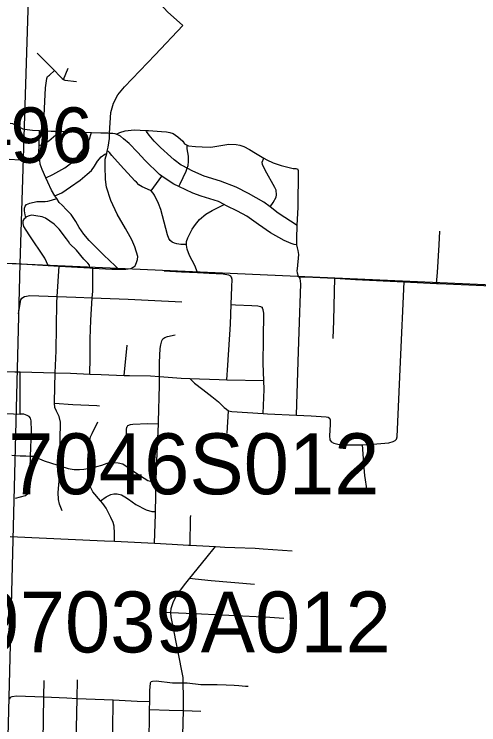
# Model space of a CAD drawing. Extents: x -157.2 to -99.3, y 12.2 to 46.2.
# Drawn here: x -146.586 to -145.747, y 36.444 to 37.727 of the extents above; entities that cross this region are included whole.
import ezdxf

# ---------------------------------------------------------------- set-up
doc = ezdxf.new("R2010")
doc.units = 0
for name, color, linetype in [('tdCoCityStreetMinor', 7, 'Continuous'), ('tdCoSectLine', 7, 'Continuous'), ('tdCoStrucPriMaintName', 7, 'Continuous'), ('tdStHwyPriRefPost1', 7, 'Continuous')]:
    doc.layers.add(name, color=color, linetype=linetype)

msp = doc.modelspace()

# ---------------------------------------------------------------- linework, layer by layer
at = {"layer": 'tdCoCityStreetMinor'}
for p, q in [((-146.4969, 37.6097), (-146.4885, 37.6301)), ((-146.3388, 37.4084), (-146.3197, 37.4352)), ((-146.3154, 37.2639), (-146.2841, 37.2624)), ((-146.0081, 37.201), (-146.0068, 37.2504)), ((-146.3875, 37.0746), (-146.3823, 37.1294)), ((-146.4497, 37.0773), (-146.4493, 37.1066)), ((-146.5753, 37.0051), (-146.5755, 37.0817)), ((-146.2017, 36.9707), (-146.199, 37.0111)), ((-146.3309, 36.829), (-146.3297, 36.8827)), ((-146.5328, 36.4942), (-146.5322, 36.5242)), ((-146.4727, 36.4916), (-146.472, 36.5254)), ((-146.3401, 36.5192), (-146.3398, 36.5199)), ((-146.2806, 36.4698), (-146.2491, 36.4687))]:
    msp.add_line(p, q, dxfattribs=at)
for points in [[(-146.4138, 37.5128), (-146.4115, 37.5497), (-146.4071, 37.5667), (-146.3988, 37.5821), (-146.3871, 37.5961), (-146.3318, 37.6543), (-146.2815, 37.7071), (-146.3093, 37.7315), (-146.3222, 37.7453), (-146.3782, 37.804), (-146.4238, 37.8455), (-146.4289, 37.7966), (-146.4298, 37.7769), (-146.4289, 37.7658), (-146.4277, 37.7623), (-146.4156, 37.7495)], [(-146.5448, 37.6572), (-146.5134, 37.6259), (-146.5132, 37.6256), (-146.5043, 37.6163), (-146.4996, 37.6114), (-146.4969, 37.6097), (-146.4945, 37.6082), (-146.4737, 37.6057)], [(-146.5329, 37.517), (-146.5327, 37.5325), (-146.5297, 37.5946), (-146.5273, 37.6116), (-146.526, 37.6148), (-146.5226, 37.6175), (-146.5132, 37.6256)], [(-146.5935, 37.5304), (-146.5896, 37.5298), (-146.5815, 37.5256), (-146.5707, 37.5206), (-146.563, 37.5191), (-146.5532, 37.5179), (-146.5405, 37.5174), (-146.5329, 37.517), (-146.5196, 37.5164), (-146.5074, 37.516), (-146.4466, 37.5136), (-146.4298, 37.513), (-146.4168, 37.513), (-146.4138, 37.5128), (-146.4081, 37.5125), (-146.4042, 37.5117), (-146.4014, 37.5105)], [(-146.398, 37.2669), (-146.4037, 37.273), (-146.4244, 37.2925), (-146.4506, 37.3187), (-146.4604, 37.3302), (-146.4688, 37.3421), (-146.4752, 37.3532), (-146.4836, 37.3658), (-146.4915, 37.3739), (-146.4996, 37.3823), (-146.5051, 37.3872), (-146.5094, 37.3944), (-146.5126, 37.3997), (-146.5186, 37.4097), (-146.5255, 37.424), (-146.529, 37.4319), (-146.5356, 37.4471), (-146.5391, 37.4565), (-146.5399, 37.4637), (-146.5416, 37.4775), (-146.5412, 37.4906), (-146.5411, 37.4965), (-146.5405, 37.5174)], [(-146.5412, 37.4906), (-146.5337, 37.493), (-146.5238, 37.4987), (-146.5154, 37.5058), (-146.511, 37.5098), (-146.5074, 37.516)], [(-146.4014, 37.5105), (-146.3953, 37.514), (-146.386, 37.5169), (-146.3692, 37.5187), (-146.3477, 37.5174), (-146.3435, 37.5172), (-146.3199, 37.5159), (-146.3112, 37.5152), (-146.3048, 37.5137), (-146.2989, 37.5117), (-146.2908, 37.5058), (-146.2814, 37.4984), (-146.2784, 37.4933), (-146.2736, 37.4911), (-146.2713, 37.49), (-146.2589, 37.4886), (-146.2466, 37.4878), (-146.2308, 37.4876), (-146.22, 37.4891), (-146.1985, 37.4928), (-146.185, 37.492), (-146.1788, 37.4908), (-146.1712, 37.4883), (-146.1608, 37.4831), (-146.1504, 37.4765), (-146.1352, 37.4675), (-146.1295, 37.4642), (-146.1184, 37.459), (-146.1036, 37.4543), (-146.0824, 37.4486), (-146.0772, 37.4486), (-146.074, 37.4476)], [(-146.0747, 37.3461), (-146.1093, 37.3682), (-146.1237, 37.3794), (-146.1352, 37.3882), (-146.1628, 37.4037), (-146.1852, 37.4153), (-146.2133, 37.4259), (-146.2427, 37.4348), (-146.2634, 37.4437), (-146.2737, 37.4491), (-146.2816, 37.4533), (-146.2843, 37.455), (-146.2974, 37.4646), (-146.3033, 37.4696), (-146.3218, 37.4866), (-146.3334, 37.4984), (-146.3423, 37.5088), (-146.347, 37.5159), (-146.3477, 37.5174)], [(-146.529, 37.4319), (-146.5164, 37.4378), (-146.4947, 37.4501), (-146.4802, 37.4607), (-146.4732, 37.4683), (-146.47, 37.473), (-146.4636, 37.4807), (-146.4592, 37.4873), (-146.452, 37.4983), (-146.4497, 37.5032), (-146.4482, 37.5084), (-146.4466, 37.5136)], [(-146.3768, 37.3253), (-146.3852, 37.3401), (-146.4, 37.3665), (-146.4116, 37.3907), (-146.4195, 37.4151), (-146.4215, 37.4289), (-146.422, 37.4531), (-146.4217, 37.4659), (-146.4191, 37.4761), (-146.418, 37.4803), (-146.4163, 37.4871), (-146.4138, 37.5029), (-146.4138, 37.5128)], [(-146.3637, 37.4781), (-146.3788, 37.4937), (-146.3889, 37.5026), (-146.3943, 37.5071), (-146.4014, 37.5105)], [(-146.2889, 37.4163), (-146.2866, 37.4212), (-146.2755, 37.4439), (-146.2737, 37.4491), (-146.272, 37.4543), (-146.2713, 37.4614), (-146.2713, 37.4711), (-146.2735, 37.4841), (-146.2736, 37.4911)], [(-146.3655, 37.4239), (-146.3684, 37.4267), (-146.3943, 37.455), (-146.4096, 37.4725), (-146.4138, 37.4775), (-146.416, 37.4792), (-146.418, 37.4803)], [(-146.0753, 37.3107), (-146.0802, 37.3113), (-146.0858, 37.3132), (-146.0982, 37.3187), (-146.1231, 37.3327), (-146.1448, 37.3478), (-146.1657, 37.3626), (-146.1825, 37.3719), (-146.2027, 37.3815), (-146.2067, 37.3837), (-146.2173, 37.3892), (-146.2483, 37.3986), (-146.2634, 37.404), (-146.2889, 37.4163), (-146.2977, 37.4205), (-146.3134, 37.4306), (-146.3197, 37.4352), (-146.3236, 37.438), (-146.3495, 37.4634), (-146.3637, 37.4781)], [(-146.5956, 37.4655), (-146.5554, 37.4632), (-146.5399, 37.4637)], [(-146.5126, 37.3997), (-146.5004, 37.405), (-146.4846, 37.4156), (-146.4668, 37.4277), (-146.4545, 37.4383), (-146.4466, 37.4454), (-146.4412, 37.4528), (-146.436, 37.4619), (-146.4291, 37.4698), (-146.4227, 37.4745), (-146.4191, 37.4761)], [(-146.1237, 37.3794), (-146.1185, 37.3875), (-146.1131, 37.3968), (-146.1124, 37.401), (-146.1129, 37.4094), (-146.1153, 37.4143), (-146.1328, 37.4459), (-146.1375, 37.4558), (-146.138, 37.4605), (-146.1352, 37.4675)], [(-146.0747, 37.3461), (-146.0733, 37.3791), (-146.0728, 37.4444), (-146.074, 37.4476)], [(-146.3388, 37.4084), (-146.3453, 37.4116), (-146.3549, 37.4158), (-146.361, 37.4195), (-146.3655, 37.4239)], [(-146.2752, 37.3112), (-146.2851, 37.3115), (-146.2925, 37.3125), (-146.2964, 37.3137), (-146.3009, 37.3159), (-146.3046, 37.3187), (-146.3068, 37.3224), (-146.3095, 37.329), (-146.3213, 37.3746), (-146.3253, 37.3855), (-146.3327, 37.4008), (-146.3354, 37.404), (-146.3388, 37.4084)], [(-146.5651, 37.3605), (-146.5662, 37.3653), (-146.5675, 37.3722), (-146.5679, 37.3769), (-146.5662, 37.3808), (-146.5638, 37.3835), (-146.5578, 37.386), (-146.5453, 37.3889), (-146.5305, 37.3894), (-146.5255, 37.3899), (-146.5189, 37.3914), (-146.5094, 37.3944)], [(-146.2752, 37.3112), (-146.2752, 37.3167), (-146.2723, 37.3238), (-146.2644, 37.3394), (-146.2587, 37.3475), (-146.2513, 37.3569), (-146.2402, 37.366), (-146.2284, 37.3732), (-146.2153, 37.3796), (-146.2067, 37.3837)], [(-146.4884, 37.3168), (-146.492, 37.3216), (-146.5048, 37.3391), (-146.5142, 37.3485), (-146.5295, 37.3591), (-146.5359, 37.3613), (-146.5472, 37.3633), (-146.5544, 37.3643), (-146.5593, 37.3635), (-146.5638, 37.3616), (-146.5651, 37.3605)], [(-146.525, 37.2737), (-146.5312, 37.2871), (-146.5593, 37.329), (-146.5689, 37.3438), (-146.5702, 37.3497), (-146.5699, 37.3542), (-146.567, 37.3591), (-146.5651, 37.3605)], [(-146.0753, 37.3107), (-146.0755, 37.3115), (-146.0757, 37.3226), (-146.0747, 37.3461)], [(-145.8233, 37.2411), (-145.8213, 37.2607), (-145.8185, 37.3106), (-145.8169, 37.3358)], [(-146.3664, 37.2758), (-146.365, 37.2787), (-146.3633, 37.2846), (-146.363, 37.2901), (-146.3682, 37.3071), (-146.3739, 37.3201), (-146.3768, 37.3253)], [(-146.4495, 37.2693), (-146.4501, 37.274), (-146.4535, 37.2777), (-146.4607, 37.2849), (-146.474, 37.3011), (-146.4856, 37.313), (-146.4884, 37.3168)], [(-146.2548, 37.261), (-146.2599, 37.2738), (-146.2696, 37.2918), (-146.2737, 37.3029), (-146.2752, 37.3103), (-146.2752, 37.3112)], [(-146.0698, 37.2501), (-146.0698, 37.2501), (-146.0712, 37.2523), (-146.0723, 37.2538), (-146.0745, 37.26), (-146.0747, 37.2646), (-146.0745, 37.2676), (-146.072, 37.2933), (-146.073, 37.3009), (-146.0745, 37.3056), (-146.0753, 37.3107)], [(-146.602, 37.278), (-146.5827, 37.277), (-146.525, 37.2737), (-146.5053, 37.2726), (-146.4826, 37.2713), (-146.4495, 37.2693), (-146.4444, 37.269), (-146.4096, 37.2669), (-146.398, 37.2669), (-146.3845, 37.2669), (-146.3753, 37.2683), (-146.3714, 37.2703), (-146.3677, 37.273), (-146.3664, 37.2758)], [(-146.5136, 37.0272), (-146.512, 37.08), (-146.5107, 37.1196), (-146.509, 37.206), (-146.5084, 37.2174), (-146.5053, 37.2726)], [(-146.4493, 37.1066), (-146.4488, 37.1411), (-146.4478, 37.1751), (-146.4452, 37.2151), (-146.4444, 37.2264), (-146.4444, 37.269)], [(-146.2841, 37.2624), (-146.2548, 37.261), (-146.2337, 37.2599)], [(-146.2337, 37.2599), (-146.2086, 37.2587), (-146.1988, 37.257), (-146.1953, 37.255), (-146.1952, 37.2548)], [(-146.2023, 37.0673), (-146.2003, 37.0938), (-146.1956, 37.1677), (-146.1942, 37.203), (-146.1929, 37.2353), (-146.1924, 37.2481), (-146.1938, 37.2526), (-146.1952, 37.2548)], [(-146.0715, 37.1535), (-146.0686, 37.2402), (-146.0698, 37.2501)], [(-146.0712, 37.2523), (-146.0597, 37.253), (-146.0068, 37.2504), (-145.9695, 37.2485), (-145.8817, 37.2441), (-145.8233, 37.2411), (-145.8193, 37.2409), (-145.7377, 37.2377), (-145.6822, 37.2347), (-145.6612, 37.2332), (-145.6373, 37.2347), (-145.5966, 37.2335), (-145.5697, 37.232), (-145.5083, 37.2261), (-145.4028, 37.2217), (-145.3228, 37.2181)], [(-145.8957, 36.9598), (-145.8945, 36.964), (-145.8881, 37.0994), (-145.8817, 37.2441)], [(-146.5786, 37.186), (-146.5758, 37.205), (-146.5746, 37.2116), (-146.5724, 37.2148), (-146.5675, 37.2176)], [(-146.5675, 37.2176), (-146.5672, 37.2178), (-146.5581, 37.2193), (-146.5084, 37.2174), (-146.4747, 37.2161), (-146.4452, 37.2151), (-146.3805, 37.2129), (-146.344, 37.2109), (-146.2836, 37.2081)], [(-146.1942, 37.203), (-146.1862, 37.2023), (-146.1569, 37.2015), (-146.1462, 37.2008), (-146.1411, 37.1995), (-146.1384, 37.1981), (-146.1381, 37.1975)], [(-146.1362, 37.0062), (-146.1347, 37.0496), (-146.1352, 37.0661), (-146.1361, 37.0967), (-146.1356, 37.1413), (-146.1354, 37.1877), (-146.1361, 37.1936), (-146.1381, 37.1975)], [(-146.0101, 37.1418), (-146.0089, 37.1739), (-146.0081, 37.201)], [(-146.3237, 37.0731), (-146.3236, 37.0982), (-146.3223, 37.1238), (-146.3211, 37.1305), (-146.3194, 37.1372), (-146.3174, 37.1409), (-146.3139, 37.1438), (-146.3093, 37.1453), (-146.2957, 37.1483)], [(-146.0762, 37.0034), (-146.0733, 37.1004), (-146.0715, 37.1535)], [(-146.9233, 37.0902), (-146.9056, 37.0898), (-146.8521, 37.0881), (-146.7784, 37.0859), (-146.7292, 37.0844), (-146.703, 37.0839), (-146.6278, 37.0825), (-146.585, 37.0817), (-146.5755, 37.0817), (-146.512, 37.08), (-146.512, 37.08)], [(-146.512, 37.08), (-146.4845, 37.0788), (-146.4499, 37.0773)], [(-146.4499, 37.0773), (-146.4497, 37.0773), (-146.4497, 37.0773)], [(-146.4497, 37.0773), (-146.429, 37.0764), (-146.3875, 37.0746), (-146.3781, 37.0749), (-146.3401, 37.0743), (-146.3237, 37.0731), (-146.2846, 37.0703), (-146.2691, 37.0697), (-146.216, 37.0676), (-146.2023, 37.0673), (-146.1352, 37.0661)], [(-146.3257, 36.9878), (-146.3255, 36.9912), (-146.3238, 37.0573), (-146.3237, 37.0731)], [(-146.2691, 37.0697), (-146.2604, 37.0612), (-146.2454, 37.0496), (-146.2294, 37.037), (-146.2168, 37.0274), (-146.2069, 37.0168), (-146.2027, 37.0138)], [(-146.5039, 36.9119), (-146.5033, 36.9586), (-146.5026, 36.9907), (-146.5048, 37.001), (-146.5097, 37.0104), (-146.5127, 37.0173), (-146.5137, 37.0247), (-146.5136, 37.0272)], [(-146.5137, 37.0247), (-146.4805, 37.0224), (-146.4371, 37.0204), (-146.4323, 37.0203)], [(-146.9283, 37.0144), (-146.9244, 37.0143), (-146.8977, 37.0138), (-146.853, 37.0125), (-146.8361, 37.0121), (-146.8156, 37.0114), (-146.7791, 37.0102), (-146.7032, 37.0078), (-146.6717, 37.0068), (-146.6285, 37.0061), (-146.5874, 37.0055), (-146.5753, 37.0051)], [(-146.5566, 36.9292), (-146.5553, 36.9747), (-146.5555, 36.993), (-146.5568, 36.9979), (-146.5592, 37.0009), (-146.5627, 37.0026), (-146.5689, 37.0048), (-146.5753, 37.0051)], [(-146.2027, 37.0138), (-146.199, 37.0111), (-146.1931, 37.0099), (-146.1362, 37.0062), (-146.1287, 37.0057), (-146.0762, 37.0034), (-146.0496, 37.0023), (-146.0227, 37.0003), (-146.019, 36.9995), (-146.0167, 36.9979)], [(-146.4532, 36.9068), (-146.453, 36.9226), (-146.4506, 36.9524), (-146.4483, 36.964), (-146.4456, 36.9704), (-146.4353, 36.9912)], [(-146.011, 36.9541), (-146.0121, 36.9547), (-146.0153, 36.9589), (-146.016, 36.9658), (-146.0148, 36.9865), (-146.0148, 36.9941), (-146.0158, 36.9973), (-146.0167, 36.9979)], [(-146.4079, 36.9178), (-146.4037, 36.9258), (-146.3911, 36.9487), (-146.3852, 36.9623), (-146.3835, 36.9692), (-146.3832, 36.9776), (-146.3825, 36.9818)], [(-146.3822, 36.9822), (-146.3808, 36.9843), (-146.3763, 36.9865), (-146.3719, 36.9872), (-146.3448, 36.9882), (-146.3257, 36.9878)], [(-146.3297, 36.8827), (-146.3292, 36.9071), (-146.3257, 36.9878)], [(-146.011, 36.9541), (-146.0084, 36.9527), (-146.0017, 36.9507), (-145.9953, 36.95), (-145.9857, 36.9497), (-145.957, 36.9499), (-145.9453, 36.95), (-145.9093, 36.9534), (-145.9016, 36.9557), (-145.8979, 36.9574), (-145.8957, 36.9598)], [(-145.9482, 36.8664), (-145.9529, 36.8942), (-145.9536, 36.9083), (-145.957, 36.9499)], [(-146.5904, 36.9312), (-146.5754, 36.9297), (-146.565, 36.9297), (-146.5566, 36.9292)], [(-146.5837, 36.8534), (-146.5661, 36.8581), (-146.5615, 36.862), (-146.5585, 36.8707), (-146.558, 36.8818), (-146.5566, 36.9292)], [(-146.5566, 36.9292), (-146.5519, 36.9289), (-146.5322, 36.921), (-146.5073, 36.9129), (-146.5039, 36.9119), (-146.4888, 36.9072), (-146.478, 36.9053), (-146.4683, 36.905), (-146.4607, 36.9055), (-146.4532, 36.9068), (-146.4459, 36.908), (-146.4279, 36.9129), (-146.418, 36.9164), (-146.4116, 36.9178), (-146.4079, 36.9178), (-146.4052, 36.9178), (-146.3983, 36.9171), (-146.3897, 36.9151), (-146.3801, 36.909), (-146.3628, 36.8969), (-146.3515, 36.8892), (-146.3446, 36.885), (-146.3352, 36.8828), (-146.3297, 36.8827)], [(-146.4996, 36.8304), (-146.5043, 36.8427), (-146.5063, 36.8511), (-146.5068, 36.8634), (-146.5041, 36.8979), (-146.5039, 36.9119)], [(-146.4305, 36.8487), (-146.4441, 36.8647), (-146.4498, 36.8753), (-146.4523, 36.8834), (-146.4533, 36.891), (-146.4532, 36.9068)], [(-146.4305, 36.8487), (-146.42, 36.856), (-146.4116, 36.8602), (-146.4062, 36.8612), (-146.4, 36.8612), (-146.3924, 36.8595), (-146.3864, 36.856), (-146.3798, 36.8513), (-146.3662, 36.8417), (-146.348, 36.8321), (-146.3376, 36.8294), (-146.3309, 36.829)], [(-146.4053, 36.7756), (-146.4049, 36.7899), (-146.4054, 36.8025), (-146.4074, 36.8094), (-146.4114, 36.8183), (-146.42, 36.8353), (-146.4264, 36.8439), (-146.4305, 36.8487)], [(-146.3328, 36.7719), (-146.331, 36.8245), (-146.3309, 36.829)], [(-146.2685, 36.7685), (-146.2678, 36.818), (-146.2673, 36.822)], [(-146.5938, 36.7843), (-146.423, 36.7765), (-146.4053, 36.7756), (-146.3328, 36.7719), (-146.3007, 36.7703), (-146.2716, 36.7687), (-146.2685, 36.7685), (-146.2225, 36.766), (-146.2225, 36.766)], [(-146.2809, 36.5196), (-146.2812, 36.5296), (-146.3004, 36.6268), (-146.3026, 36.6388), (-146.3034, 36.6465), (-146.3033, 36.6469), (-146.3026, 36.6539), (-146.2987, 36.6665), (-146.2925, 36.6781), (-146.2787, 36.6968), (-146.2687, 36.709), (-146.24, 36.7441), (-146.2225, 36.766)], [(-146.2225, 36.766), (-146.2059, 36.7651), (-146.1875, 36.7641), (-146.1507, 36.7629), (-146.1362, 36.7621), (-146.0838, 36.7581)], [(-146.2687, 36.709), (-146.2595, 36.7074), (-146.2301, 36.7047), (-146.1522, 36.6978)], [(-146.323, 36.6478), (-146.3033, 36.6469), (-146.2479, 36.6445), (-146.1241, 36.6384), (-146.0992, 36.6366)], [(-146.3425, 36.4055), (-146.3416, 36.4716), (-146.3414, 36.4861), (-146.3411, 36.5062), (-146.3401, 36.5192)], [(-146.3398, 36.5199), (-146.3389, 36.522), (-146.3362, 36.5229), (-146.33, 36.5232), (-146.3004, 36.52), (-146.2893, 36.5197), (-146.2809, 36.5196)], [(-146.2819, 36.4027), (-146.2806, 36.4698), (-146.2802, 36.4936), (-146.2809, 36.5196)], [(-146.2809, 36.5196), (-146.274, 36.5195), (-146.2489, 36.5168), (-146.2193, 36.5168), (-146.2035, 36.5162), (-146.1886, 36.5153)], [(-146.1886, 36.5153), (-146.1806, 36.5148), (-146.1684, 36.514), (-146.1634, 36.5137)], [(-146.5939, 36.4904), (-146.5939, 36.4911), (-146.5929, 36.4936), (-146.5897, 36.4953), (-146.582, 36.4963), (-146.5328, 36.4942), (-146.4913, 36.4924), (-146.4727, 36.4916)], [(-146.5357, 36.3496), (-146.5352, 36.3614), (-146.5342, 36.4146), (-146.5328, 36.4942)], [(-146.4754, 36.3463), (-146.4745, 36.3885), (-146.4741, 36.4116), (-146.4727, 36.4916)], [(-146.4727, 36.4916), (-146.4075, 36.4888), (-146.364, 36.4869), (-146.3414, 36.4861)], [(-146.4088, 36.4086), (-146.4082, 36.4337), (-146.4075, 36.4888)], [(-146.3416, 36.4716), (-146.3063, 36.4707), (-146.2806, 36.4698)]]:
    msp.add_lwpolyline(points, dxfattribs=at)
at = {"layer": 'tdCoSectLine'}
for points in [[(-146.5753, 37.2765), (-146.544, 38.27)], [(-147.5685, 37.3179), (-146.5753, 37.2765)], [(-146.6009, 36.2799), (-146.5753, 37.2765)], [(-146.5753, 37.2765), (-145.5734, 37.2322)]]:
    msp.add_lwpolyline(points, dxfattribs=at)

# ---------------------------------------------------------------- texts
at = {"layer": 'tdCoStrucPriMaintName'}
for s, p in [('97046S012', (-146.6788, 36.8604)), ('97039A012', (-146.6582, 36.5747))]:
    msp.add_text(s, height=0.11, dxfattribs=at).set_placement(p)
at = {"layer": 'tdStHwyPriRefPost1'}
msp.add_text('‒‒96', height=0.1, dxfattribs=at).set_placement((-146.7419, 37.4591))

doc.saveas('drawing.dxf')
